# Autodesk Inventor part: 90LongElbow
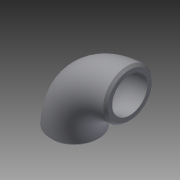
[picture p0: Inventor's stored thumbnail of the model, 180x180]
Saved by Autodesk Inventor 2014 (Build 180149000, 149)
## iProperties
Created: 2004-05
Part Number: 90LongElbow
Document SubType Name: Modeling
Designer: dayb
Manufacturer: Standard
Standards Organization: Custom
Density: 1 g/cm^3
Material: Generic
Appearance: Default
Author: dayb
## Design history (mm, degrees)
sketch "Sketch2"
  geometry: L1 (-55.189, 0)-(9.198, 0) reference; L2 (0, 55.189)-(0, -9.198) reference; A1 r 38.1 centre (0, 0) between (0, 38.1) and (-38.1, 0)
  constraints: 3 point on line, 2 point on circle, 1 centre point
  dimensions: "d7" = 38.1 distance of A1.start A1.centre (= G)
workplane "Work Plane1"
sketch "Sketch3"
  geometry: C1 r 16.7 at (0, 0); C2 r 12.154 at (0, 0)
  constraints: 2 centre point, 1 coincident
  dimensions: "d8" = 24.3078 diameter of C2 (= ID); "d9" = 33.401 diameter of C1 (= OD)
sweep "Sweep1" sketch "Sketch3" dims "d10" = 0
chamfer "Chamfer2" distance "d11" = 1.51553 (= t); stored, may be unused: second distance "d12" = 3.175, angle "d13" = 45 deg
workpoint "Work Point1"
workaxis "Work Axis1"
workpoint "Work Point2"
workaxis "Work Axis2"
body "Solid1"
other parameters: "OD" = 33.401 [user parameter; used in 2 equation terms], "ID" = 24.3078 [user parameter; used in 2 equation terms], "G" = 38.1 [user parameter; used in 1 equation term], "t" = 1.51553 (= -0.166667 x ID + 0.166667 x OD) [user parameter; used in 1 equation term]
